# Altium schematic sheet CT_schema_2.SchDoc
size 461 x 227 mm
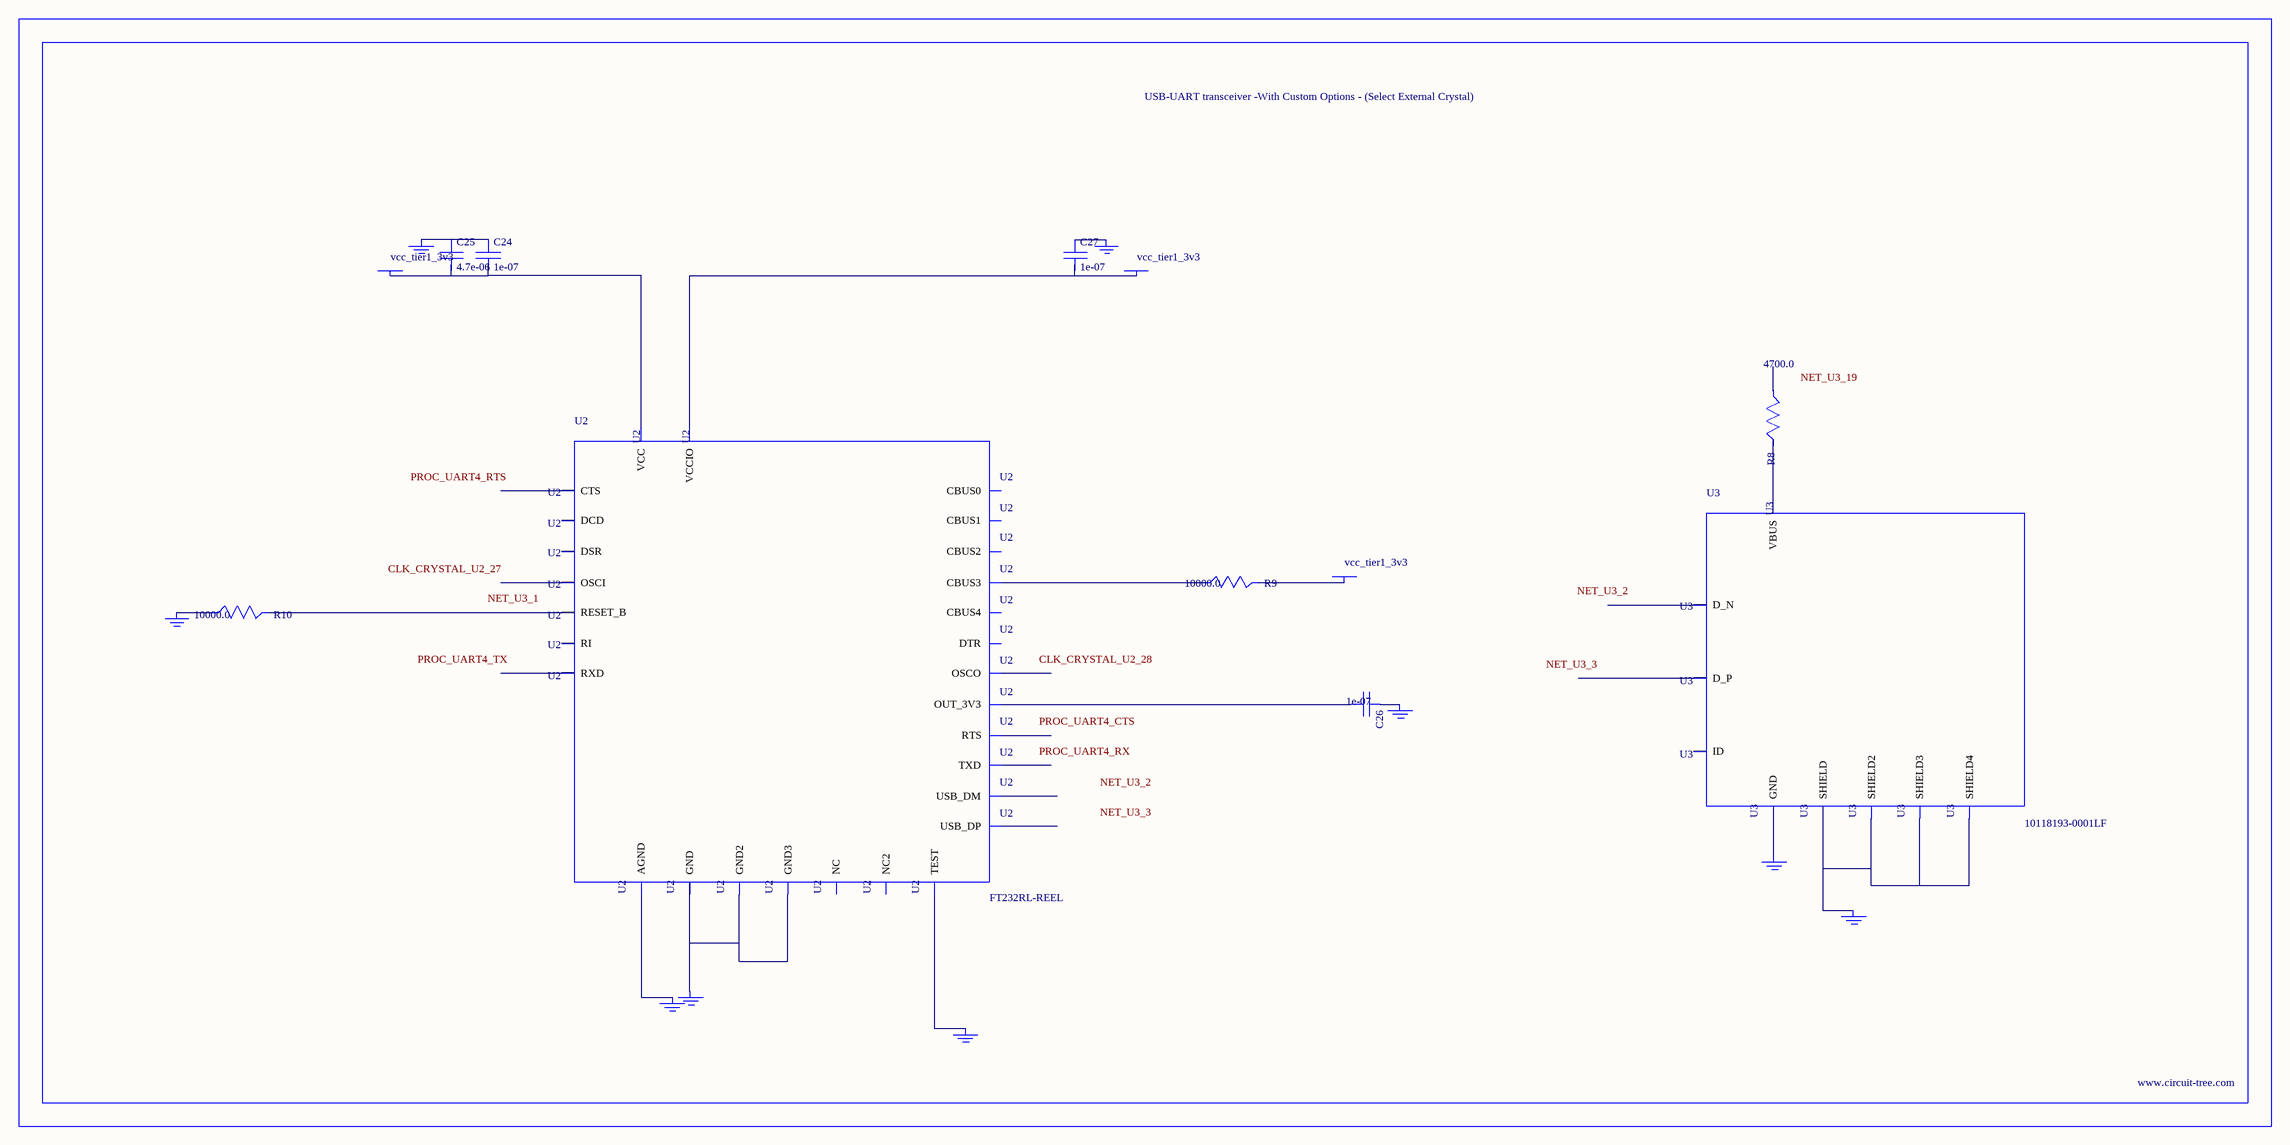
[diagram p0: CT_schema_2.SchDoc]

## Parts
BORDER1  (no value)
C24  1e-07  [C0402]
C25  4.7e-06  [C0805]
C26  1e-07  [C0402]
C27  1e-07  [C0402]
GND_INSTANCE_1_0  (no value)
GND_INSTANCE_1_1  (no value)
GND_INSTANCE_1_2  (no value)
GND_INSTANCE_1_3  (no value)
GND_INSTANCE_1_4  (no value)
GND_INSTANCE_1_5  (no value)
GND_INSTANCE_1_6  (no value)
GND_INSTANCE_1_7  (no value)
GND_INSTANCE_1_8  (no value)
POWER_INSTANCE_1_0  vcc_tier1_3v3
POWER_INSTANCE_1_1  vcc_tier1_3v3
POWER_INSTANCE_1_2  vcc_tier1_3v3
R8  4700.0  [R0603]
R9  10000.0  [R0603]
R10  10000.0  [R0603]
U2  FT232RL-REEL  [SSOP-28]
U3  10118193-0001LF  [FCI_10118193-0001LF]

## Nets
NetC24_1: C24.1 C25.1 GND_INSTANCE_1_3.0(GND)
NetC24_2: C24.2 C25.2 POWER_INSTANCE_1_2.0(PWR) U2.20(VCC)
NetC26_1: C26.1 GND_INSTANCE_1_1.0(GND)
NetC26_2: C26.2 U2.17(OUT_3V3)
NetC27_1: C27.1 GND_INSTANCE_1_0.0(GND)
NetC27_2: C27.2 POWER_INSTANCE_1_0.0(PWR) U2.4(VCCIO)
NetGND_INSTANCE_1_2_0: GND_INSTANCE_1_2.0(GND) R10.1
NetGND_INSTANCE_1_4_0: GND_INSTANCE_1_4.0(GND) U2.25(AGND)
NetGND_INSTANCE_1_5_0: GND_INSTANCE_1_5.0(GND) U2.26(TEST)
NetGND_INSTANCE_1_6_0: GND_INSTANCE_1_6.0(GND) U2.7(GND) U2.18(GND2) U2.21(GND3)
NetGND_INSTANCE_1_7_0: GND_INSTANCE_1_7.0(GND) U3.6(SHIELD) U3.7(SHIELD2) U3.8(SHIELD3) U3.9(SHIELD4)
NetGND_INSTANCE_1_8_0: GND_INSTANCE_1_8.0(GND) U3.5(GND)
NetPOWER_INSTANCE_1_1_0: POWER_INSTANCE_1_1.0(PWR) R9.2
NetR8_2: R8.2 U3.1(VBUS)
NetR9_1: R9.1 U2.14(CBUS3)
NetR10_2: R10.2 U2.19(RESET_B)

Not connected (* = marked no-connect by the designer): R8 1; U2 1(TXD) 2(DTR) 3(RTS) 5(RXD) 6(RI) 8(NC) 9(DSR) 10(DCD) 11(CTS) 12(CBUS4) 13(CBUS2) 15(USB_DP) 16(USB_DM) 22(CBUS1) 23(CBUS0) 24(NC2) 27(OSCI) 28(OSCO); U3 2(D_N) 3(D_P) 4(ID)

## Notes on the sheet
- Labels drawn without touching a wire or pin: CLK_CRYSTAL_U2_27, CLK_CRYSTAL_U2_28, NET_U3_1, NET_U3_2, NET_U3_3, NET_U3_19, PROC_UART4_CTS, PROC_UART4_RTS, PROC_UART4_RX, PROC_UART4_TX

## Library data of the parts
BORDER1 = BORDER_PAGE1
C24 C26 C27 = C0402C104K3RACTU
C25 = C0805C475K4RACTU
GND_INSTANCE_1_0-GND_INSTANCE_1_8 = GND
POWER_INSTANCE_1_0-POWER_INSTANCE_1_2 = PWR
R8 = RC0603JR-074K7L
R9 R10 = RC0603JR-0710KL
